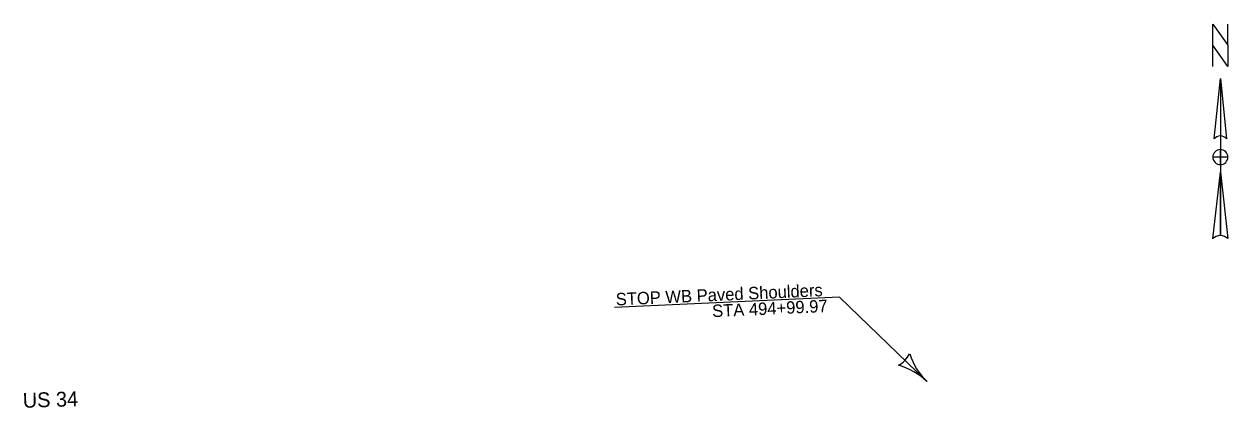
# Model space of a CAD drawing. Extents: x 22712865 to 22760106, y 6235088 to 6238602.
# Drawn here: x 22726035 to 22727552, y 6235973 to 6236456 of the extents above; entities that cross this region are included whole.
import ezdxf

# ---------------------------------------------------------------- set-up
doc = ezdxf.new("R2010")
doc.units = 0
for name, color, linetype in [('Default', 7, 'Continuous'), ('Draft_3', 7, 'Continuous'), ('dsnTextOdd', 7, 'Continuous')]:
    doc.layers.add(name, color=color, linetype=linetype)

msp = doc.modelspace()

# ---------------------------------------------------------------- linework, layer by layer
at = {"layer": 'Draft_3'}
msp.add_lwpolyline([(22727172.6, 6236006.3), (22727062.4, 6236112.6), (22726778.8, 6236099.8)], dxfattribs=at)
for centre, radius, start, end in [((22727121.3, 6236055.8), 32.8, 298.3045, 333.7712), ((22727231.7, 6236067.5), 85, 197.9654, 226.0379), ((22727113.6, 6235945.1), 85, 46.0379, 74.1104)]:
    msp.add_arc(centre, radius, start, end, dxfattribs=at)
at = {"layer": 'dsnTextOdd'}
for p, q in [((22727542.2, 6236387.8), (22727549.8, 6236311.8)), ((22727542.2, 6236387.8), (22727542.2, 6236190.1)), ((22727534.6, 6236311.8), (22727534.6, 6236311.8)), ((22727534.9, 6236312.5), (22727536.3, 6236314)), ((22727542.2, 6236279.4), (22727542.2, 6236279.4)), ((22727532.7, 6236186.2), (22727542.2, 6236269.9))]:
    msp.add_line(p, q, dxfattribs=at)
msp.add_lwpolyline([(22727551.7, 6236403), (22727532.7, 6236429.6), (22727532.7, 6236456.3), (22727551.7, 6236429.6)], close=True, dxfattribs=at)
for points in [[(22727532.7, 6236403), (22727532.7, 6236456.3), (22727551.7, 6236429.6), (22727551.7, 6236456.3)], [(22727534.6, 6236311.8), (22727542.2, 6236387.8), (22727542.2, 6236315.6)], [(22727551.7, 6236288.9), (22727542.2, 6236288.9), (22727542.2, 6236298.4)], [(22727542.2, 6236279.4), (22727542.2, 6236288.9), (22727532.7, 6236288.9)], [(22727542.2, 6236190.1), (22727542.2, 6236269.9), (22727551.7, 6236186.3)]]:
    msp.add_lwpolyline(points, dxfattribs=at)
for centre, radius, start, end in [((22727542.2, 6236306), 9.51, 90.0204, 143.1257), ((22727542.2, 6236306.1), 9.5, 36.8481, 90.0218), ((22727542.2, 6236288.9), 9.51, 90, 180), ((22727542.2, 6236288.9), 9.51, 0, 90), ((22727542.2, 6236288.9), 9.51, 180, 270), ((22727542.2, 6236288.9), 9.51, 270, 360), ((22727542.2, 6236176.3), 13.8, 89.9894, 133.619), ((22727542.2, 6236176.3), 13.8, 46.4021, 90.0006)]:
    msp.add_arc(centre, radius, start, end, dxfattribs=at)

# ---------------------------------------------------------------- texts
at = {"layer": 'Default'}
msp.add_text('US 34', height=18.75, rotation=1.7877, dxfattribs=at).set_placement((22726033.8, 6235973.3))
at = {"layer": 'Draft_3'}
for s, p in [('STOP WB Paved Shoulders', (22726780.9, 6236102.1)), ('STA 494+99.97', (22726902.3, 6236087.4))]:
    msp.add_text(s, height=15.601, rotation=2.5911, dxfattribs=at).set_placement(p)

doc.saveas('drawing.dxf')
